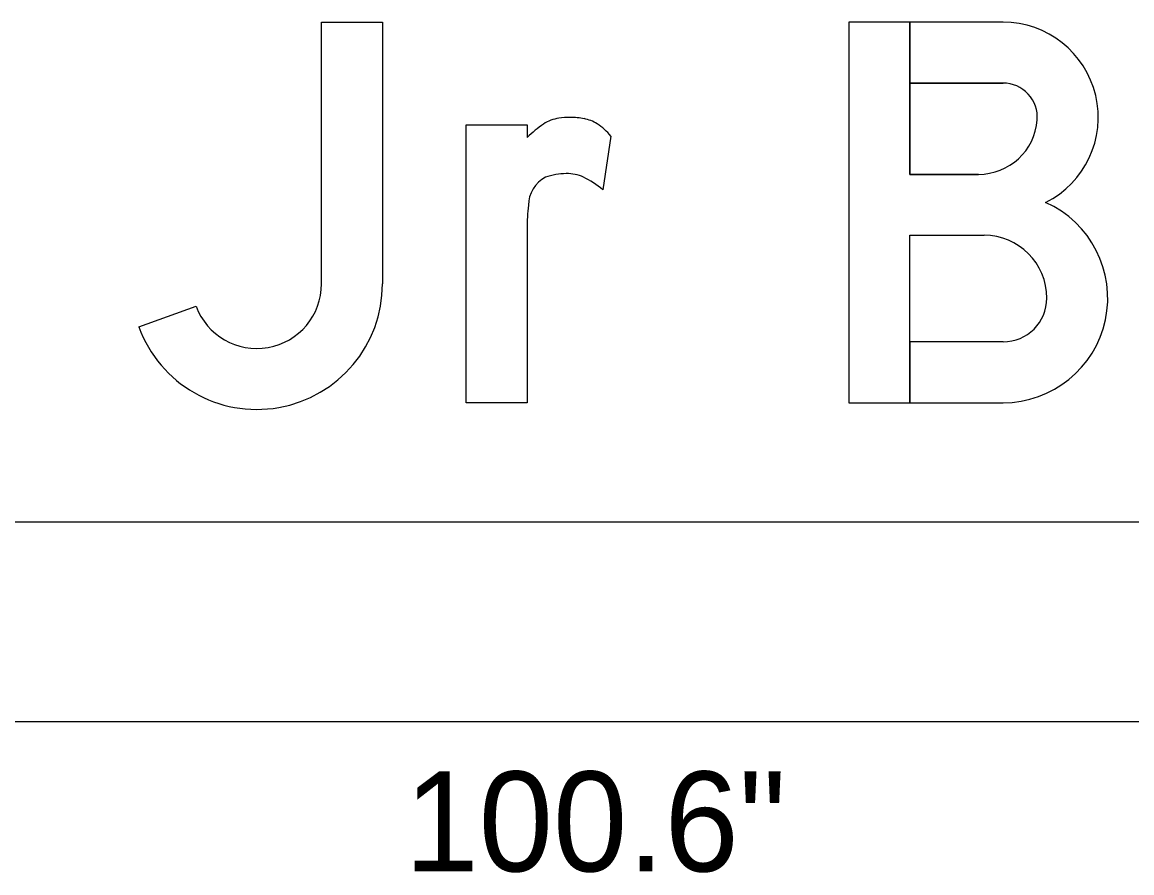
# Model space of a CAD drawing. Extents: x 1374 to 1480, y 568 to 638.
# Drawn here: x 1418.297 to 1420.24, y 624.529 to 626.019 of the extents above; entities that cross this region are included whole.
import ezdxf

# ---------------------------------------------------------------- set-up
doc = ezdxf.new("R2010")
doc.units = 0
for name, color, linetype in [('GSBWFill', 7, 'Continuous'), ('GSColorFill', 7, 'Continuous'), ('GSDims', 7, 'Continuous'), ('GSOutline', 7, 'Continuous')]:
    doc.layers.add(name, color=color, linetype=linetype)

msp = doc.modelspace()

# ---------------------------------------------------------------- linework, layer by layer
at = {"layer": 'GSBWFill'}
for p, q in [((1419.3278, 625.8192), (1419.3136, 625.7253)), ((1419.3278, 625.8192), (1419.3278, 625.8192)), ((1419.8511, 625.6454), (1419.9811, 625.6454)), ((1418.5011, 625.4849), (1418.6013, 625.5215)), ((1418.5011, 625.4849), (1418.5011, 625.4849)), ((1414.8581, 625.1437), (1423.8581, 625.1437))]:
    msp.add_line(p, q, dxfattribs=at)
for points in [[(1418.8211, 625.5604), (1418.8211, 626.0187), (1418.9278, 626.0187), (1418.9278, 625.5604)], [(1419.9712, 625.752), (1419.8511, 625.752), (1419.8511, 626.0187), (1419.7444, 626.0187), (1419.7444, 625.352), (1419.8511, 625.352), (1419.8511, 625.6454)], [(1420.0144, 626.0187), (1419.8511, 626.0187), (1419.8511, 625.912), (1420.0144, 625.912)], [(1419.1811, 625.6572), (1419.1811, 625.352), (1419.0744, 625.352), (1419.0744, 625.8387), (1419.1811, 625.8387), (1419.1811, 625.8168)], [(1420.0144, 625.4587), (1419.8511, 625.4587), (1419.8511, 625.352), (1420.0144, 625.352)]]:
    msp.add_lwpolyline(points, dxfattribs=at)
for centre, major_axis, ratio, start_param, end_param in [((1420.0144, 625.852), (0, 0.1667), 0.999999, 3.604547, 6.283185), ((1420.0144, 625.852), (0, 0.06), 0.999999, 4.63539, 6.283185), ((1419.2465, 625.7846), (0, 0.0667), 0.999998, 0.152837, 0.581368), ((1419.2568, 625.7175), (0, 0.1345), 0.999998, 0, 0.152837), ((1419.2568, 625.7272), (0, 0.1248), 0.999998, 6.089185, 6.283185), ((1419.268, 625.7843), (0, 0.0667), 0.999998, 5.719052, 6.089185), ((1419.9712, 625.8554), (0, 0.1033), 0.999999, 3.141593, 4.63539), ((1419.3093, 625.689), (0, 0.181), 0.999998, 0.581368, 0.786698), ((1419.2503, 625.7563), (0, 0.0997), 0.999998, 5.39423, 5.719052), ((1419.2497, 625.6461), (0, 0.1073), 0.999998, 0, 0.348596), ((1419.2497, 625.6752), (0, 0.0783), 0.999998, 5.88958, 6.283185), ((1419.239, 625.6976), (0, 0.0558), 0.999998, 0.483758, 1.563151), ((1419.1945, 625.5806), (0, 0.1873), 0.999998, 5.594805, 5.811282), ((1419.5837, 625.6572), (0, 0.4026), 0.999998, 1.469323, 1.570796), ((1420.0144, 625.5354), (0, 0.1833), 0.999999, 3.141593, 5.865119), ((1419.9811, 625.5354), (0, 0.11), 0.999999, 4.712389, 6.283185), ((1418.7078, 625.5604), (0, 0.22), 0.999999, 1.920734, 4.712389), ((1418.7078, 625.5604), (0, 0.1133), 0.999999, 1.920734, 4.712389), ((1420.0144, 625.5354), (0, 0.0767), 0.999999, 3.141593, 4.712389)]:
    msp.add_ellipse(centre, major_axis=major_axis, ratio=ratio, start_param=start_param, end_param=end_param, dxfattribs=at)
at = {"layer": 'GSColorFill'}
for p, q in [((1419.3278, 625.8192), (1419.3136, 625.7253)), ((1419.3278, 625.8192), (1419.3278, 625.8192)), ((1419.8511, 625.6454), (1419.9811, 625.6454)), ((1418.5011, 625.4849), (1418.6013, 625.5215)), ((1418.5011, 625.4849), (1418.5011, 625.4849)), ((1414.8581, 625.1437), (1423.8581, 625.1437)), ((1414.8581, 625.1437), (1423.8581, 625.1437))]:
    msp.add_line(p, q, dxfattribs=at)
for points in [[(1418.8211, 625.5604), (1418.8211, 626.0187), (1418.9278, 626.0187), (1418.9278, 625.5604)], [(1419.9712, 625.752), (1419.8511, 625.752), (1419.8511, 626.0187), (1419.7444, 626.0187), (1419.7444, 625.352), (1419.8511, 625.352), (1419.8511, 625.6454)], [(1420.0144, 626.0187), (1419.8511, 626.0187), (1419.8511, 625.912), (1420.0144, 625.912)], [(1419.1811, 625.6572), (1419.1811, 625.352), (1419.0744, 625.352), (1419.0744, 625.8387), (1419.1811, 625.8387), (1419.1811, 625.8168)], [(1420.0144, 625.4587), (1419.8511, 625.4587), (1419.8511, 625.352), (1420.0144, 625.352)]]:
    msp.add_lwpolyline(points, dxfattribs=at)
for centre, major_axis, ratio, start_param, end_param in [((1420.0144, 625.852), (0, 0.1667), 0.999999, 3.604547, 6.283185), ((1420.0144, 625.852), (0, 0.06), 0.999999, 4.63539, 6.283185), ((1419.2465, 625.7846), (0, 0.0667), 0.999998, 0.152837, 0.581368), ((1419.2568, 625.7175), (0, 0.1345), 0.999998, 0, 0.152837), ((1419.2568, 625.7272), (0, 0.1248), 0.999998, 6.089185, 6.283185), ((1419.268, 625.7843), (0, 0.0667), 0.999998, 5.719052, 6.089185), ((1419.9712, 625.8554), (0, 0.1033), 0.999999, 3.141593, 4.63539), ((1419.3093, 625.689), (0, 0.181), 0.999998, 0.581368, 0.786698), ((1419.2503, 625.7563), (0, 0.0997), 0.999998, 5.39423, 5.719052), ((1419.2497, 625.6461), (0, 0.1073), 0.999998, 0, 0.348596), ((1419.2497, 625.6752), (0, 0.0783), 0.999998, 5.88958, 6.283185), ((1419.239, 625.6976), (0, 0.0558), 0.999998, 0.483758, 1.563151), ((1419.1945, 625.5806), (0, 0.1873), 0.999998, 5.594805, 5.811282), ((1419.5837, 625.6572), (0, 0.4026), 0.999998, 1.469323, 1.570796), ((1420.0144, 625.5354), (0, 0.1833), 0.999999, 3.141593, 5.865119), ((1419.9811, 625.5354), (0, 0.11), 0.999999, 4.712389, 6.283185), ((1418.7078, 625.5604), (0, 0.22), 0.999999, 1.920734, 4.712389), ((1418.7078, 625.5604), (0, 0.1133), 0.999999, 1.920734, 4.712389), ((1420.0144, 625.5354), (0, 0.0767), 0.999999, 3.141593, 4.712389)]:
    msp.add_ellipse(centre, major_axis=major_axis, ratio=ratio, start_param=start_param, end_param=end_param, dxfattribs=at)
at = {"layer": 'GSDims'}
msp.add_line((1415.1678, 624.7937), (1423.5478, 624.7937), dxfattribs=at)
at = {"layer": 'GSOutline'}
for p, q in [((1420.0144, 625.912), (1419.8511, 625.912)), ((1419.3278, 625.8192), (1419.3136, 625.7253)), ((1419.3278, 625.8192), (1419.3278, 625.8192)), ((1419.8511, 625.6454), (1419.9811, 625.6454)), ((1418.5011, 625.4849), (1418.6013, 625.5215)), ((1418.5011, 625.4849), (1418.5011, 625.4849)), ((1419.7444, 625.352), (1420.0144, 625.352)), ((1414.8581, 625.1437), (1423.8581, 625.1437))]:
    msp.add_line(p, q, dxfattribs=at)
for points in [[(1418.8211, 625.5604), (1418.8211, 626.0187), (1418.9278, 626.0187), (1418.9278, 625.5604)], [(1420.0144, 626.0187), (1419.7444, 626.0187), (1419.7444, 625.352)], [(1419.8511, 625.912), (1419.8511, 625.752), (1419.9712, 625.752)], [(1419.1811, 625.6572), (1419.1811, 625.352), (1419.0744, 625.352), (1419.0744, 625.8387), (1419.1811, 625.8387), (1419.1811, 625.8168)], [(1420.0144, 625.4587), (1419.8511, 625.4587), (1419.8511, 625.6454)]]:
    msp.add_lwpolyline(points, dxfattribs=at)
for centre, major_axis, ratio, start_param, end_param in [((1420.0144, 625.852), (0, 0.1667), 0.999999, 3.604547, 6.283185), ((1420.0144, 625.852), (0, 0.06), 0.999999, 4.63539, 6.283185), ((1419.2465, 625.7846), (0, 0.0667), 0.999998, 0.152837, 0.581368), ((1419.2568, 625.7175), (0, 0.1345), 0.999998, 0, 0.152837), ((1419.2568, 625.7272), (0, 0.1248), 0.999998, 6.089185, 6.283185), ((1419.268, 625.7843), (0, 0.0667), 0.999998, 5.719052, 6.089185), ((1419.9712, 625.8554), (0, 0.1033), 0.999999, 3.141593, 4.63539), ((1419.3093, 625.689), (0, 0.181), 0.999998, 0.581368, 0.786698), ((1419.2503, 625.7563), (0, 0.0997), 0.999998, 5.39423, 5.719052), ((1419.2497, 625.6461), (0, 0.1073), 0.999998, 0, 0.348596), ((1419.2497, 625.6752), (0, 0.0783), 0.999998, 5.88958, 6.283185), ((1419.239, 625.6976), (0, 0.0558), 0.999998, 0.483758, 1.563151), ((1419.1945, 625.5806), (0, 0.1873), 0.999998, 5.594805, 5.811282), ((1419.5837, 625.6572), (0, 0.4026), 0.999998, 1.469323, 1.570796), ((1420.0144, 625.5354), (0, 0.1833), 0.999999, 3.141593, 5.865119), ((1419.9811, 625.5354), (0, 0.11), 0.999999, 4.712389, 6.283185), ((1418.7078, 625.5604), (0, 0.22), 0.999999, 1.920734, 4.712389), ((1418.7078, 625.5604), (0, 0.1133), 0.999999, 1.920734, 4.712389), ((1420.0144, 625.5354), (0, 0.0767), 0.999999, 3.141593, 4.712389)]:
    msp.add_ellipse(centre, major_axis=major_axis, ratio=ratio, start_param=start_param, end_param=end_param, dxfattribs=at)

# ---------------------------------------------------------------- texts
at = {"layer": 'GSDims'}
msp.add_text('100.6"', height=0.175, dxfattribs=at).set_placement((1418.9661, 624.5312))

doc.saveas('drawing.dxf')
